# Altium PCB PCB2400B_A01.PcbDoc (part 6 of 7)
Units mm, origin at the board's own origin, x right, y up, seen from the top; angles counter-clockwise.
Board outline 115 x 60 mm, 6 copper layers (Top Layer, Signal Layer 2, Signal Layer 3, Signal Layer 4, Signal Layer 5, Bottom Layer), stack 1.555 mm thick; 382 components, 308 nets, 1384 pads, 1152 vias.
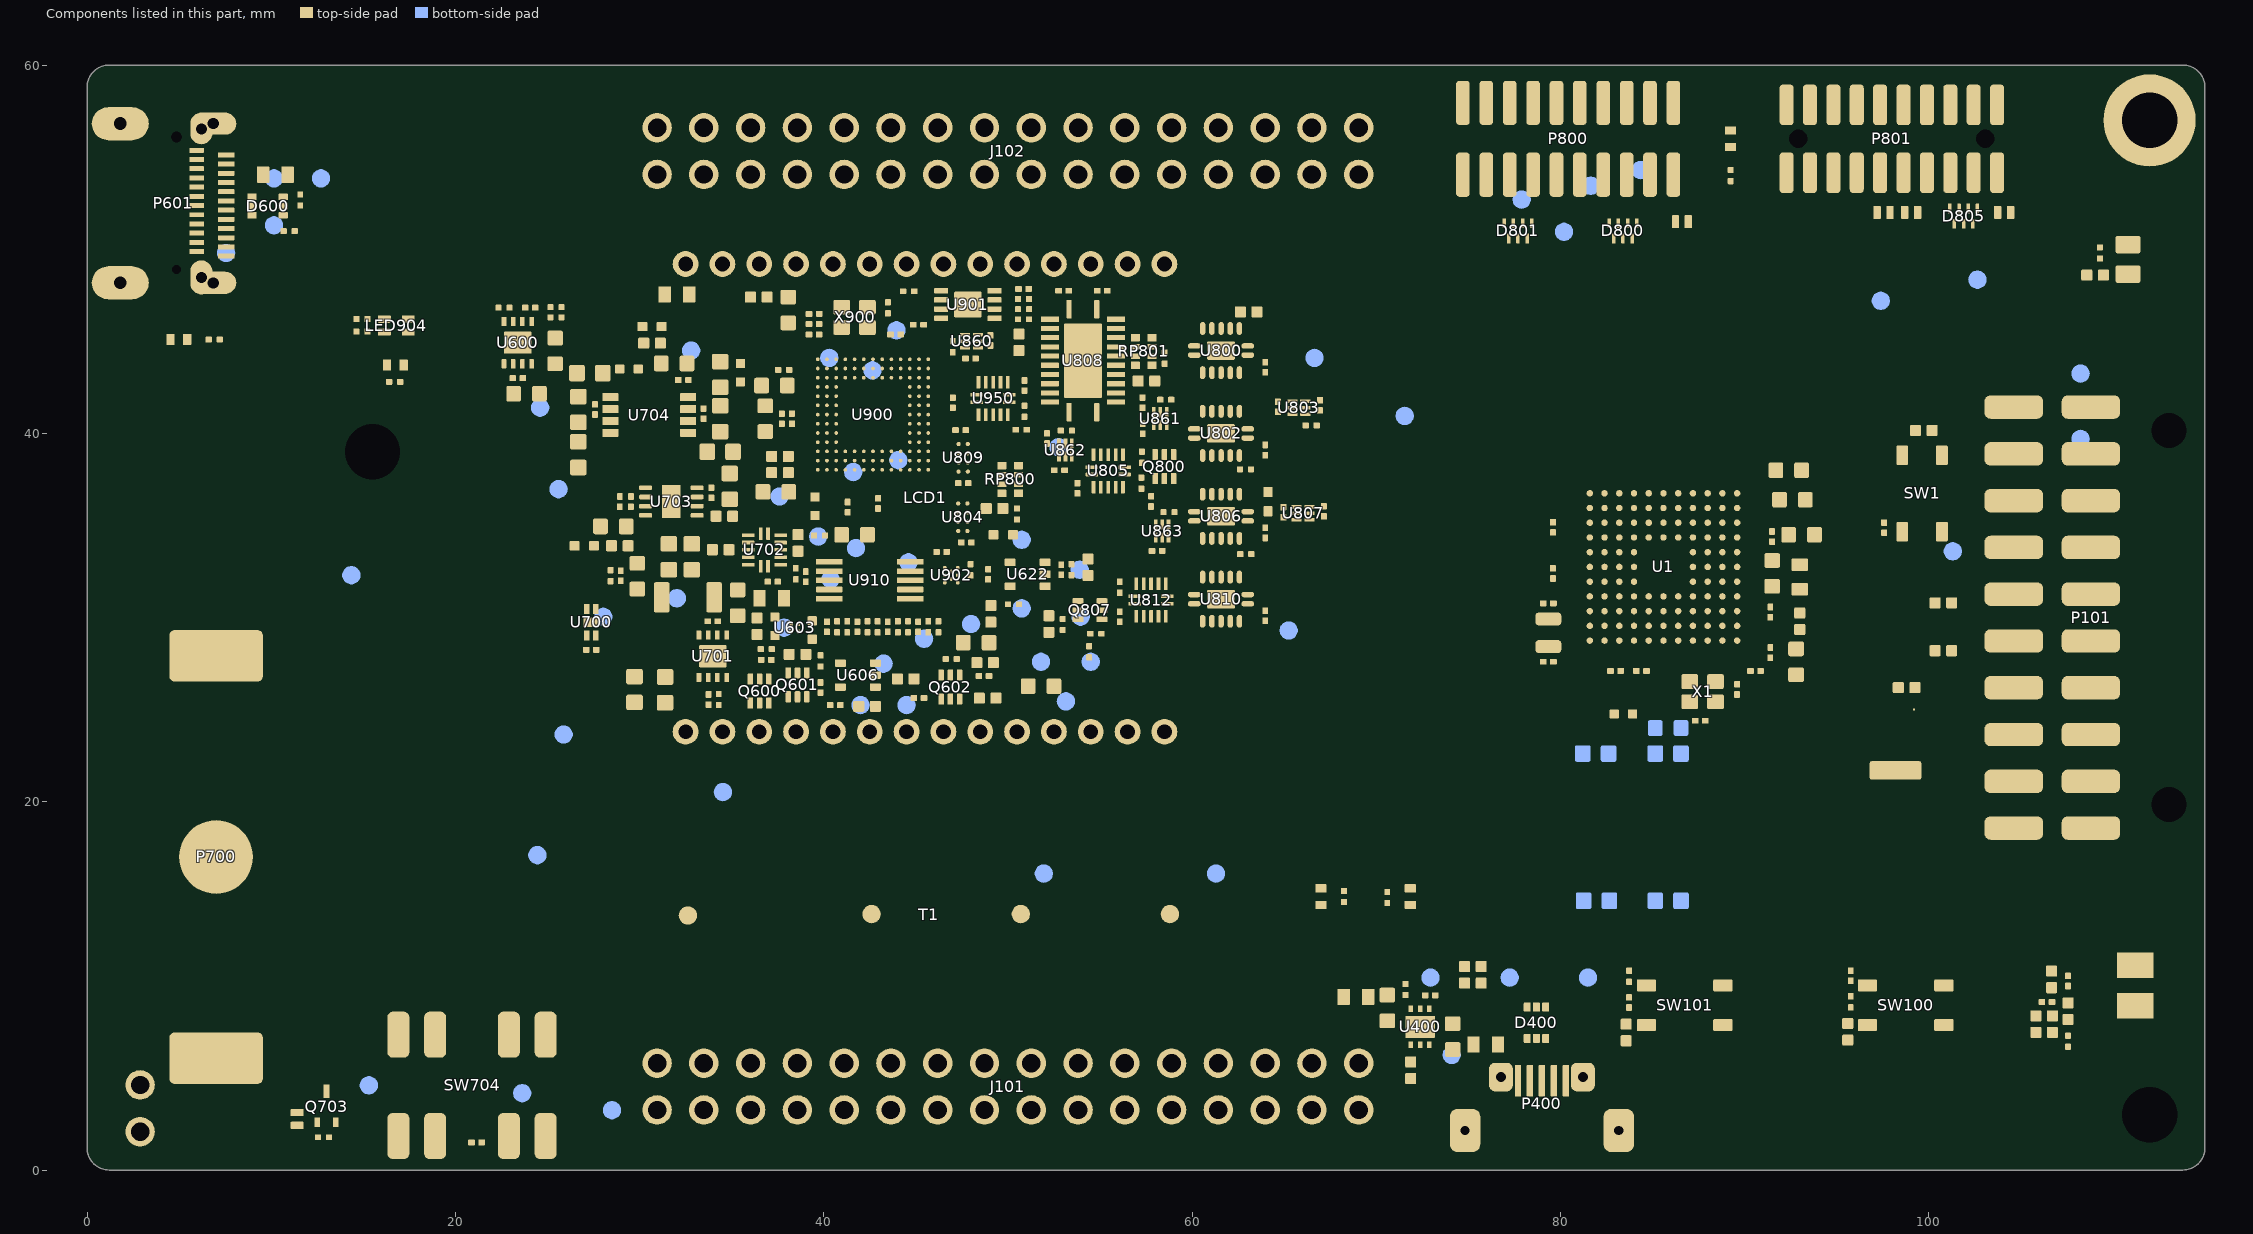
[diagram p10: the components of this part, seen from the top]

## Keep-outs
Bottom Layer:
  region: 68.25,54.063 ccw(c69.05,54.063) 69.05,53.263 ccw(c69.05,54.063) 69.85,54.063 ccw(c69.05,54.063) 69.05,54.863 ccw(c69.05,54.063)
  region: 65.71,54.063 ccw(c66.51,54.063) 66.51,53.263 ccw(c66.51,54.063) 67.31,54.063 ccw(c66.51,54.063) 66.51,54.863 ccw(c66.51,54.063)
  region: 42.85,54.063 ccw(c43.65,54.063) 43.65,53.263 ccw(c43.65,54.063) 44.45,54.063 ccw(c43.65,54.063) 43.65,54.863 ccw(c43.65,54.063)
  region: 40.31,54.063 ccw(c41.11,54.063) 41.11,53.263 ccw(c41.11,54.063) 41.91,54.063 ccw(c41.11,54.063) 41.11,54.863 ccw(c41.11,54.063)
  region: 37.77,54.063 ccw(c38.57,54.063) 38.57,53.263 ccw(c38.57,54.063) 39.37,54.063 ccw(c38.57,54.063) 38.57,54.863 ccw(c38.57,54.063)
  region: 35.23,54.063 ccw(c36.03,54.063) 36.03,53.263 ccw(c36.03,54.063) 36.83,54.063 ccw(c36.03,54.063) 36.03,54.863 ccw(c36.03,54.063)
  region: 32.69,54.063 ccw(c33.49,54.063) 33.49,53.263 ccw(c33.49,54.063) 34.29,54.063 ccw(c33.49,54.063) 33.49,54.863 ccw(c33.49,54.063)
  region: 68.25,56.603 ccw(c69.05,56.603) 69.05,55.803 ccw(c69.05,56.603) 69.85,56.603 ccw(c69.05,56.603) 69.05,57.403 ccw(c69.05,56.603)
  region: 65.71,56.603 ccw(c66.51,56.603) 66.51,55.803 ccw(c66.51,56.603) 67.31,56.603 ccw(c66.51,56.603) 66.51,57.403 ccw(c66.51,56.603)
  region: 63.17,56.603 ccw(c63.97,56.603) 63.97,55.803 ccw(c63.97,56.603) 64.77,56.603 ccw(c63.97,56.603) 63.97,57.403 ccw(c63.97,56.603)
  region: 60.63,56.603 ccw(c61.43,56.603) 61.43,55.803 ccw(c61.43,56.603) 62.23,56.603 ccw(c61.43,56.603) 61.43,57.403 ccw(c61.43,56.603)
  region: 58.09,56.603 ccw(c58.89,56.603) 58.89,55.803 ccw(c58.89,56.603) 59.69,56.603 ccw(c58.89,56.603) 58.89,57.403 ccw(c58.89,56.603)
  region: 53.01,56.603 ccw(c53.81,56.603) 53.81,55.803 ccw(c53.81,56.603) 54.61,56.603 ccw(c53.81,56.603) 53.81,57.403 ccw(c53.81,56.603)
  region: 50.47,56.603 ccw(c51.27,56.603) 51.27,55.803 ccw(c51.27,56.603) 52.07,56.603 ccw(c51.27,56.603) 51.27,57.403 ccw(c51.27,56.603)
  region: 47.93,56.603 ccw(c48.73,56.603) 48.73,55.803 ccw(c48.73,56.603) 49.53,56.603 ccw(c48.73,56.603) 48.73,57.403 ccw(c48.73,56.603)
  region: 45.39,56.603 ccw(c46.19,56.603) 46.19,55.803 ccw(c46.19,56.603) 46.99,56.603 ccw(c46.19,56.603) 46.19,57.403 ccw(c46.19,56.603)
  region: 42.85,56.603 ccw(c43.65,56.603) 43.65,55.803 ccw(c43.65,56.603) 44.45,56.603 ccw(c43.65,56.603) 43.65,57.403 ccw(c43.65,56.603)
  region: 40.31,56.603 ccw(c41.11,56.603) 41.11,55.803 ccw(c41.11,56.603) 41.91,56.603 ccw(c41.11,56.603) 41.11,57.403 ccw(c41.11,56.603)
  region: 37.77,56.603 ccw(c38.57,56.603) 38.57,55.803 ccw(c38.57,56.603) 39.37,56.603 ccw(c38.57,56.603) 38.57,57.403 ccw(c38.57,56.603)
  region: 35.23,56.603 ccw(c36.03,56.603) 36.03,55.803 ccw(c36.03,56.603) 36.83,56.603 ccw(c36.03,56.603) 36.03,57.403 ccw(c36.03,56.603)
  region: 32.69,56.603 ccw(c33.49,56.603) 33.49,55.803 ccw(c33.49,56.603) 34.29,56.603 ccw(c33.49,56.603) 33.49,57.403 ccw(c33.49,56.603)
  region: 68.25,3.263 ccw(c69.05,3.263) 69.05,2.463 ccw(c69.05,3.263) 69.85,3.263 ccw(c69.05,3.263) 69.05,4.063 ccw(c69.05,3.263)
  region: 65.71,3.263 ccw(c66.51,3.263) 66.51,2.463 ccw(c66.51,3.263) 67.31,3.263 ccw(c66.51,3.263) 66.51,4.063 ccw(c66.51,3.263)
  region: 63.17,3.263 ccw(c63.97,3.263) 63.97,2.463 ccw(c63.97,3.263) 64.77,3.263 ccw(c63.97,3.263) 63.97,4.063 ccw(c63.97,3.263)
  region: 60.63,3.263 ccw(c61.43,3.263) 61.43,2.463 ccw(c61.43,3.263) 62.23,3.263 ccw(c61.43,3.263) 61.43,4.063 ccw(c61.43,3.263)
  region: 58.09,3.263 ccw(c58.89,3.263) 58.89,2.463 ccw(c58.89,3.263) 59.69,3.263 ccw(c58.89,3.263) 58.89,4.063 ccw(c58.89,3.263)
  region: 55.55,3.263 ccw(c56.35,3.263) 56.35,2.463 ccw(c56.35,3.263) 57.15,3.263 ccw(c56.35,3.263) 56.35,4.063 ccw(c56.35,3.263)
  region: 53.01,3.263 ccw(c53.81,3.263) 53.81,2.463 ccw(c53.81,3.263) 54.61,3.263 ccw(c53.81,3.263) 53.81,4.063 ccw(c53.81,3.263)
  region: 50.47,3.263 ccw(c51.27,3.263) 51.27,2.463 ccw(c51.27,3.263) 52.07,3.263 ccw(c51.27,3.263) 51.27,4.063 ccw(c51.27,3.263)
  region: 47.93,3.263 ccw(c48.73,3.263) 48.73,2.463 ccw(c48.73,3.263) 49.53,3.263 ccw(c48.73,3.263) 48.73,4.063 ccw(c48.73,3.263)
  region: 45.39,3.263 ccw(c46.19,3.263) 46.19,2.463 ccw(c46.19,3.263) 46.99,3.263 ccw(c46.19,3.263) 46.19,4.063 ccw(c46.19,3.263)
  region: 42.85,3.263 ccw(c43.65,3.263) 43.65,2.463 ccw(c43.65,3.263) 44.45,3.263 ccw(c43.65,3.263) 43.65,4.063 ccw(c43.65,3.263)
  region: 40.31,3.263 ccw(c41.11,3.263) 41.11,2.463 ccw(c41.11,3.263) 41.91,3.263 ccw(c41.11,3.263) 41.11,4.063 ccw(c41.11,3.263)
  region: 37.77,3.263 ccw(c38.57,3.263) 38.57,2.463 ccw(c38.57,3.263) 39.37,3.263 ccw(c38.57,3.263) 38.57,4.063 ccw(c38.57,3.263)
  region: 35.23,3.263 ccw(c36.03,3.263) 36.03,2.463 ccw(c36.03,3.263) 36.83,3.263 ccw(c36.03,3.263) 36.03,4.063 ccw(c36.03,3.263)
  region: 32.69,3.263 ccw(c33.49,3.263) 33.49,2.463 ccw(c33.49,3.263) 34.29,3.263 ccw(c33.49,3.263) 33.49,4.063 ccw(c33.49,3.263)
  region: 30.15,5.803 ccw(c30.95,5.803) 30.95,5.003 ccw(c30.95,5.803) 31.75,5.803 ccw(c30.95,5.803) 30.95,6.603 ccw(c30.95,5.803)
  region: 68.25,5.803 ccw(c69.05,5.803) 69.05,5.003 ccw(c69.05,5.803) 69.85,5.803 ccw(c69.05,5.803) 69.05,6.603 ccw(c69.05,5.803)
  region: 65.71,5.803 ccw(c66.51,5.803) 66.51,5.003 ccw(c66.51,5.803) 67.31,5.803 ccw(c66.51,5.803) 66.51,6.603 ccw(c66.51,5.803)
  region: 63.17,5.803 ccw(c63.97,5.803) 63.97,5.003 ccw(c63.97,5.803) 64.77,5.803 ccw(c63.97,5.803) 63.97,6.603 ccw(c63.97,5.803)
  region: 60.63,5.803 ccw(c61.43,5.803) 61.43,5.003 ccw(c61.43,5.803) 62.23,5.803 ccw(c61.43,5.803) 61.43,6.603 ccw(c61.43,5.803)
  region: 58.09,5.803 ccw(c58.89,5.803) 58.89,5.003 ccw(c58.89,5.803) 59.69,5.803 ccw(c58.89,5.803) 58.89,6.603 ccw(c58.89,5.803)
  region: 55.55,5.803 ccw(c56.35,5.803) 56.35,5.003 ccw(c56.35,5.803) 57.15,5.803 ccw(c56.35,5.803) 56.35,6.603 ccw(c56.35,5.803)
  region: 53.01,5.803 ccw(c53.81,5.803) 53.81,5.003 ccw(c53.81,5.803) 54.61,5.803 ccw(c53.81,5.803) 53.81,6.603 ccw(c53.81,5.803)
  region: 50.47,5.803 ccw(c51.27,5.803) 51.27,5.003 ccw(c51.27,5.803) 52.07,5.803 ccw(c51.27,5.803) 51.27,6.603 ccw(c51.27,5.803)
  region: 47.93,5.803 ccw(c48.73,5.803) 48.73,5.003 ccw(c48.73,5.803) 49.53,5.803 ccw(c48.73,5.803) 48.73,6.603 ccw(c48.73,5.803)
  region: 45.39,5.803 ccw(c46.19,5.803) 46.19,5.003 ccw(c46.19,5.803) 46.99,5.803 ccw(c46.19,5.803) 46.19,6.603 ccw(c46.19,5.803)
  region: 42.85,5.803 ccw(c43.65,5.803) 43.65,5.003 ccw(c43.65,5.803) 44.45,5.803 ccw(c43.65,5.803) 43.65,6.603 ccw(c43.65,5.803)
  region: 40.31,5.803 ccw(c41.11,5.803) 41.11,5.003 ccw(c41.11,5.803) 41.91,5.803 ccw(c41.11,5.803) 41.11,6.603 ccw(c41.11,5.803)
  region: 37.77,5.803 ccw(c38.57,5.803) 38.57,5.003 ccw(c38.57,5.803) 39.37,5.803 ccw(c38.57,5.803) 38.57,6.603 ccw(c38.57,5.803)
  region: 35.23,5.803 ccw(c36.03,5.803) 36.03,5.003 ccw(c36.03,5.803) 36.83,5.803 ccw(c36.03,5.803) 36.03,6.603 ccw(c36.03,5.803)
  region: 32.69,5.803 ccw(c33.49,5.803) 33.49,5.003 ccw(c33.49,5.803) 34.29,5.803 ccw(c33.49,5.803) 33.49,6.603 ccw(c33.49,5.803)
  region: 103.499,19.001 cw(c103.499,18.501) 103.999,18.501 cw(c103.499,18.501) 103.499,18.001 cw(c103.499,18.501) 102.999,18.501 cw(c103.499,18.501)
  region: 108.249,40.201 cw(c108.249,39.7) 108.749,39.701 cw(c108.249,39.701) 108.249,39.201 cw(c108.249,39.701) 107.749,39.701 cw(c108.249,39.7)
  region: 108.249,43.749 cw(c108.249,43.249) 108.749,43.249 cw(c108.249,43.249) 108.249,42.749 cw(c108.249,43.249) 107.749,43.249 cw(c108.249,43.249)
  region: 106.999,54.201 cw(c106.999,53.701) 107.499,53.701 cw(c106.999,53.701) 106.999,53.201 cw(c106.999,53.701) 106.499,53.701 cw(c106.999,53.701)
  region: 105.399,52.499 cw(c105.399,51.999) 105.899,51.999 cw(c105.399,51.999) 105.399,51.499 cw(c105.399,51.999) 104.899,51.999 cw(c105.399,51.999)
  region: 104.449,54.201 cw(c104.449,53.701) 104.949,53.701 cw(c104.449,53.701) 104.449,53.201 cw(c104.449,53.701) 103.949,53.701 cw(c104.449,53.701)
  region: 103.398,52.499 cw(c103.398,51.999) 103.898,51.999 cw(c103.398,51.999) 103.398,51.499 cw(c103.398,51.999) 102.898,51.999 cw(c103.398,51.999)
  region: 102.648,48.849 cw(c102.648,48.349) 103.148,48.349 cw(c102.648,48.349) 102.648,47.849 cw(c102.648,48.349) 102.148,48.349 cw(c102.648,48.349)
  region: 97.398,47.701 cw(c97.398,47.201) 97.898,47.201 cw(c97.398,47.201) 97.398,46.701 cw(c97.398,47.201) 96.898,47.201 cw(c97.398,47.201)
  region: 92.524,52.433 cw(c92.524,51.933) 93.024,51.933 cw(c92.524,51.933) 92.524,51.433 cw(c92.524,51.933) 92.024,51.933 cw(c92.524,51.933)
  region: 93.54,54.211 cw(c93.54,53.711) 94.04,53.711 cw(c93.54,53.711) 93.54,53.211 cw(c93.54,53.711) 93.04,53.711 cw(c93.54,53.711)
  region: 90.492,52.433 cw(c90.492,51.933) 90.992,51.933 cw(c90.492,51.933) 90.492,51.433 cw(c90.492,51.933) 89.992,51.933 cw(c90.492,51.933)
  region: 88.46,52.433 cw(c88.46,51.933) 88.96,51.933 cw(c88.46,51.933) 88.46,51.433 cw(c88.46,51.933) 87.96,51.933 cw(c88.46,51.933)
  region: 89.476,54.211 cw(c89.476,53.711) 89.976,53.711 cw(c89.476,53.711) 89.476,53.211 cw(c89.476,53.711) 88.976,53.711 cw(c89.476,53.711)
  region: 87.465,54.207 cw(c87.466,53.707) 87.966,53.707 cw(c87.465,53.708) 87.465,53.207 cw(c87.465,53.707) 86.966,53.707 cw(c87.466,53.707)
  region: 84.348,54.8 cw(c84.348,54.3) 84.848,54.301 cw(c84.348,54.301) 84.348,53.8 cw(c84.348,54.3) 83.848,54.3 cw(c84.348,54.3)
  region: 85.399,52.199 cw(c85.399,51.699) 85.899,51.7 cw(c85.399,51.7) 85.399,51.2 cw(c85.399,51.699) 84.899,51.699 cw(c85.399,51.699)
  region: 93.448,42.799 cw(c93.448,42.299) 93.949,42.299 cw(c93.448,42.299) 93.448,41.799 cw(c93.448,42.299) 92.948,42.299 cw(c93.449,42.299)
  region: 86.148,40.051 cw(c86.149,39.551) 86.649,39.551 cw(c86.148,39.551) 86.148,39.051 cw(c86.148,39.551) 85.649,39.551 cw(c86.149,39.551)
  region: 81.648,53.95 cw(c81.648,53.45) 82.148,53.45 cw(c81.648,53.45) 81.648,52.95 cw(c81.648,53.45) 81.148,53.45 cw(c81.648,53.449)
  region: 77.899,53.2 cw(c77.899,52.7) 78.399,52.7 cw(c77.898,52.7) 77.899,52.2 cw(c77.899,52.7) 77.399,52.7 cw(c77.899,52.7)
  region: 80.2,51.45 cw(c80.2,50.95) 80.7,50.95 cw(c80.2,50.95) 80.2,50.45 cw(c80.2,50.95) 79.7,50.95 cw(c80.2,50.95)
  region: 77.398,48.499 cw(c77.398,47.999) 77.898,47.999 cw(c77.398,47.999) 77.398,47.499 cw(c77.398,47.999) 76.898,47.999 cw(c77.398,47.999)
  region: 75.399,48.499 cw(c75.399,47.999) 75.899,47.999 cw(c75.399,47.999) 75.399,47.499 cw(c75.399,47.999) 74.899,47.999 cw(c75.399,47.999)
  region: 73.398,48.499 cw(c73.398,47.999) 73.898,47.999 cw(c73.398,47.999) 73.398,47.499 cw(c73.398,47.999) 72.898,47.999 cw(c73.398,47.999)
  region: 77.398,46.299 cw(c77.398,45.799) 77.898,45.799 cw(c77.398,45.799) 77.398,45.299 cw(c77.398,45.799) 76.898,45.799 cw(c77.398,45.799)
  region: 75.399,46.299 cw(c75.399,45.799) 75.899,45.799 cw(c75.399,45.799) 75.399,45.299 cw(c75.399,45.799) 74.899,45.799 cw(c75.399,45.799)
  region: 73.398,46.299 cw(c73.398,45.799) 73.898,45.799 cw(c73.398,45.799) 73.398,45.299 cw(c73.398,45.799) 72.898,45.799 cw(c73.398,45.799)
  region: 71.399,46.299 cw(c71.399,45.799) 71.899,45.799 cw(c71.399,45.799) 71.399,45.299 cw(c71.399,45.799) 70.899,45.799 cw(c71.399,45.799)
  region: 73.398,43.599 cw(c73.398,43.099) 73.898,43.099 cw(c73.398,43.099) 73.398,42.599 cw(c73.398,43.099) 72.898,43.099 cw(c73.398,43.099)
  region: 71.549,41.45 cw(c71.549,40.95) 72.049,40.95 cw(c71.548,40.95) 71.549,40.45 cw(c71.549,40.95) 71.049,40.95 cw(c71.549,40.95)
  region: 66.649,44.6 cw(c66.649,44.1) 67.149,44.1 cw(c66.649,44.1) 66.649,43.6 cw(c66.649,44.1) 66.149,44.1 cw(c66.649,44.1)
  region: 94.198,12.349 cw(c94.198,11.849) 94.698,11.849 cw(c94.198,11.85) 94.198,11.349 cw(c94.198,11.849) 93.698,11.849 cw(c94.198,11.849)
  region: 96.799,11.801 cw(c96.799,11.301) 97.299,11.301 cw(c96.799,11.301) 96.799,10.801 cw(c96.799,11.301) 96.299,11.301 cw(c96.799,11.301)
  region: 93.248,9.949 cw(c93.248,9.449) 93.748,9.449 cw(c93.248,9.449) 93.248,8.949 cw(c93.248,9.449) 92.748,9.449 cw(c93.248,9.449)
  region: 96.499,9.149 cw(c96.499,8.649) 96.999,8.649 cw(c96.499,8.649) 96.499,8.149 cw(c96.499,8.649) 95.999,8.649 cw(c96.499,8.649)
  region: 95.699,6.551 cw(c95.699,6.051) 96.199,6.051 cw(c95.699,6.051) 95.699,5.551 cw(c95.699,6.051) 95.199,6.051 cw(c95.699,6.05)
  region: 93.248,7.399 cw(c93.248,6.899) 93.748,6.899 cw(c93.248,6.899) 93.248,6.399 cw(c93.248,6.899) 92.748,6.899 cw(c93.248,6.899)
  region: 81.498,10.95 cw(c81.498,10.45) 81.998,10.45 cw(c81.498,10.45) 81.498,9.95 cw(c81.498,10.45) 80.998,10.45 cw(c81.498,10.45)
  region: 77.248,10.95 cw(c77.248,10.45) 77.748,10.45 cw(c77.248,10.45) 77.248,9.95 cw(c77.248,10.45) 76.748,10.45 cw(c77.248,10.45)
  region: 72.948,10.95 cw(c72.948,10.45) 73.448,10.45 cw(c72.948,10.45) 72.948,9.95 cw(c72.948,10.45) 72.448,10.45 cw(c72.948,10.45)
  region: 74.099,6.749 cw(c74.099,6.249) 74.599,6.249 cw(c74.099,6.249) 74.099,5.749 cw(c74.099,6.249) 73.599,6.249 cw(c74.099,6.249)
  region: 54.673,41.625 cw(c54.673,41.125) 55.173,41.126 cw(c54.673,41.126) 54.673,40.626 cw(c54.673,41.125) 54.173,41.125 cw(c54.673,41.125)
  region: 52.747,39.751 cw(c52.748,39.251) 53.248,39.251 cw(c52.747,39.251) 52.747,38.751 cw(c52.747,39.251) 52.248,39.251 cw(c52.748,39.251)
  region: 50.749,34.724 cw(c50.749,34.224) 51.249,34.224 cw(c50.748,34.224) 50.749,33.724 cw(c50.749,34.224) 50.249,34.224 cw(c50.749,34.224)
  region: 53.898,33.099 cw(c53.898,32.599) 54.398,32.599 cw(c53.898,32.599) 53.898,32.099 cw(c53.898,32.599) 53.398,32.599 cw(c53.898,32.599)
  region: 50.749,31.001 cw(c50.749,30.501) 51.249,30.501 cw(c50.748,30.501) 50.749,30.001 cw(c50.749,30.501) 50.249,30.501 cw(c50.749,30.501)
  region: 53.949,30.551 cw(c53.949,30.051) 54.449,30.051 cw(c53.949,30.051) 53.949,29.551 cw(c53.949,30.051) 53.449,30.051 cw(c53.949,30.051)
  region: 54.498,28.1 cw(c54.498,27.6) 54.998,27.6 cw(c54.497,27.6) 54.498,27.1 cw(c54.498,27.6) 53.998,27.6 cw(c54.498,27.6)
  region: 51.798,28.1 cw(c51.798,27.6) 52.298,27.6 cw(c51.797,27.6) 51.798,27.1 cw(c51.798,27.6) 51.298,27.6 cw(c51.798,27.6)
  region: 53.149,25.951 cw(c53.149,25.451) 53.649,25.451 cw(c53.149,25.451) 53.149,24.951 cw(c53.149,25.451) 52.649,25.451 cw(c53.149,25.451)
  region: 47.998,30.15 cw(c47.998,29.65) 48.498,29.65 cw(c47.998,29.65) 47.998,29.15 cw(c47.998,29.65) 47.498,29.65 cw(c47.998,29.65)
  region: 45.448,29.35 cw(c45.448,28.85) 45.948,28.85 cw(c45.447,28.85) 45.448,28.35 cw(c45.448,28.85) 44.948,28.85 cw(c45.448,28.85)
  region: 46.999,25.75 cw(c47,25.25) 47.5,25.251 cw(c46.999,25.251) 46.999,24.751 cw(c46.999,25.25) 46.499,25.25 cw(c47,25.25)
  region: 43.248,28.001 cw(c43.248,27.501) 43.748,27.501 cw(c43.248,27.501) 43.248,27.001 cw(c43.248,27.501) 42.748,27.501 cw(c43.248,27.501)
  region: 44.498,25.75 cw(c44.498,25.25) 44.998,25.251 cw(c44.497,25.251) 44.498,24.751 cw(c44.498,25.25) 43.998,25.25 cw(c44.498,25.25)
  region: 41.998,25.75 cw(c41.998,25.25) 42.498,25.251 cw(c41.998,25.251) 41.998,24.751 cw(c41.998,25.25) 41.498,25.25 cw(c41.998,25.25)
  region: 61.3,16.599 cw(c61.3,16.099) 61.8,16.099 cw(c61.3,16.099) 61.3,15.599 cw(c61.3,16.099) 60.8,16.099 cw(c61.3,16.099)
  region: 51.95,16.599 cw(c51.95,16.099) 52.45,16.099 cw(c51.95,16.099) 51.95,15.599 cw(c51.95,16.099) 51.45,16.099 cw(c51.95,16.099)
  region: 34.523,21.026 cw(c34.523,20.526) 35.023,20.526 cw(c34.523,20.526) 34.523,20.026 cw(c34.523,20.526) 34.023,20.526 cw(c34.523,20.526)
  region: 24.449,17.6 cw(c24.449,17.1) 24.949,17.1 cw(c24.449,17.1) 24.449,16.6 cw(c24.449,17.1) 23.949,17.1 cw(c24.449,17.099)
  region: 15.648,26.449 cw(c15.648,25.949) 16.148,25.949 cw(c15.648,25.949) 15.648,25.449 cw(c15.648,25.949) 15.148,25.949 cw(c15.648,25.949)
  region: 12.049,26.449 cw(c12.049,25.949) 12.549,25.949 cw(c12.049,25.949) 12.049,25.449 cw(c12.049,25.949) 11.549,25.949 cw(c12.049,25.949)
  region: 12.024,29.774 cw(c12.024,29.274) 12.524,29.274 cw(c12.024,29.274) 12.024,28.774 cw(c12.024,29.274) 11.524,29.274 cw(c12.024,29.274)
  region: 9.474,29.799 cw(c9.474,29.299) 9.974,29.299 cw(c9.473,29.299) 9.474,28.799 cw(c9.474,29.299) 8.974,29.299 cw(c9.474,29.299)
  region: 14.348,32.799 cw(c14.348,32.299) 14.848,32.299 cw(c14.348,32.299) 14.348,31.799 cw(c14.348,32.299) 13.848,32.299 cw(c14.348,32.299)
  region: 10.398,32.25 cw(c10.398,31.75) 10.898,31.75 cw(c10.398,31.751) 10.398,31.25 cw(c10.398,31.75) 9.898,31.75 cw(c10.398,31.75)
  region: 10.398,34.9 cw(c10.398,34.4) 10.898,34.4 cw(c10.398,34.4) 10.398,33.9 cw(c10.398,34.4) 9.898,34.4 cw(c10.398,34.399)
  region: 18.445,49.045 cw(c18.445,48.545) 18.945,48.545 cw(c18.445,48.545) 18.445,48.045 cw(c18.445,48.545) 17.945,48.545 cw(c18.445,48.545)
  region: 15.905,50.315 cw(c15.905,49.815) 16.405,49.815 cw(c15.905,49.815) 15.905,49.315 cw(c15.905,49.815) 15.405,49.815 cw(c15.905,49.815)
  region: 18.445,51.585 cw(c18.445,51.085) 18.945,51.085 cw(c18.445,51.085) 18.445,50.585 cw(c18.445,51.085) 17.945,51.085 cw(c18.445,51.085)
  region: 15.905,52.855 cw(c15.905,52.355) 16.405,52.355 cw(c15.905,52.355) 15.905,51.855 cw(c15.905,52.355) 15.405,52.355 cw(c15.905,52.355)
  region: 18.445,54.125 cw(c18.445,53.625) 18.945,53.625 cw(c18.445,53.625) 18.445,53.125 cw(c18.445,53.625) 17.945,53.625 cw(c18.445,53.625)
  region: 15.905,55.395 cw(c15.905,54.895) 16.405,54.895 cw(c15.905,54.895) 15.905,54.395 cw(c15.905,54.895) 15.405,54.895 cw(c15.905,54.895)
  region: 12.699,54.351 cw(c12.699,53.851) 13.199,53.851 cw(c12.699,53.851) 12.699,53.351 cw(c12.699,53.851) 12.199,53.851 cw(c12.699,53.851)
  region: 10.149,54.351 cw(c10.149,53.851) 10.649,53.851 cw(c10.149,53.851) 10.149,53.351 cw(c10.149,53.851) 9.649,53.851 cw(c10.149,53.851)
  region: 10.149,51.801 cw(c10.149,51.301) 10.649,51.301 cw(c10.149,51.301) 10.149,50.801 cw(c10.149,51.301) 9.649,51.301 cw(c10.149,51.301)
  region: 7.548,50.3 cw(c7.548,49.8) 8.048,49.8 cw(c7.548,49.8) 7.548,49.3 cw(c7.548,49.8) 7.048,49.8 cw(c7.548,49.799)
  region: 24.599,41.9 cw(c24.599,41.4) 25.099,41.4 cw(c24.599,41.4) 24.599,40.9 cw(c24.599,41.4) 24.099,41.4 cw(c24.599,41.4)
  region: 36.248,37.549 cw(c36.248,37.049) 36.748,37.049 cw(c36.248,37.049) 36.248,36.549 cw(c36.248,37.049) 35.748,37.049 cw(c36.248,37.049)
  region: 38.974,37.544 cw(c38.974,37.044) 39.474,37.044 cw(c38.974,37.045) 38.974,36.544 cw(c38.974,37.044) 38.474,37.044 cw(c38.974,37.044)
  region: 41.599,38.4 cw(c41.599,37.9) 42.1,37.9 cw(c41.599,37.9) 41.599,37.4 cw(c41.599,37.9) 41.099,37.9 cw(c41.6,37.9)
  region: 44.048,39.05 cw(c44.048,38.55) 44.548,38.55 cw(c44.048,38.55) 44.048,38.05 cw(c44.048,38.55) 43.548,38.55 cw(c44.048,38.55)
  region: 42.648,43.924 cw(c42.648,43.424) 43.149,43.424 cw(c42.648,43.424) 42.648,42.924 cw(c42.648,43.424) 42.148,43.424 cw(c42.649,43.424)
  region: 43.949,46.101 cw(c43.949,45.601) 44.449,45.601 cw(c43.949,45.601) 43.949,45.101 cw(c43.949,45.601) 43.449,45.601 cw(c43.949,45.601)
  region: 18.445,46.505 cw(c18.445,46.005) 18.945,46.005 cw(c18.445,46.005) 18.445,45.505 cw(c18.445,46.005) 17.945,46.005 cw(c18.445,46.005)

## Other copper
Top Layer:
  pour cut-out: 49.006,49.758 49.006,49.626 49.941,49.626 49.941,49.758
  pour cut-out: 81.277,39.88 81.277,39.748 82.213,39.748 82.213,39.88
  pour cut-out: 82.507,38.77 82.375,38.77 82.375,37.834 82.507,37.834
  pour cut-out: 79.273,36.008 79.405,36.008 79.405,36.944 79.273,36.944
  pour cut-out: 87.991,31.141 87.991,31.009 88.927,31.009 88.927,31.141
  pour cut-out: 83.065,31.244 83.065,31.112 84.001,31.112 84.001,31.244
  pour cut-out: 82.54,32.712 82.408,32.712 82.408,31.776 82.54,31.776
  pour cut-out: 84.06,32.563 84.06,32.695 83.124,32.695 83.124,32.563
  pour cut-out: 85.695,34.177 85.695,34.309 84.759,34.309 84.759,34.177
  pour cut-out: 110.23,39.736 110.23,39.868 109.294,39.868 109.294,39.736
  pour cut-out: 106.576,42.161 106.708,42.161 106.708,43.096 106.576,43.096
  pour cut-out: 63.206,28.537 63.338,28.537 63.338,29.473 63.206,29.473
  pour cut-out: 57.033,23.359 57.033,23.227 57.969,23.227 57.969,23.359
  pour cut-out: 50.37,25.758 50.238,25.758 50.238,24.594 50.37,24.594
  pour cut-out: 51.99,23.304 51.99,23.436 51.054,23.436 51.054,23.304
  pour cut-out: 48.884,31.949 48.884,32.081 47.948,32.081 47.948,31.949
  pour cut-out: 22.043,42.65 22.394,42.65 22.394,43.244 22.043,43.244
  pour cut-out: 37.212,25.167 37.212,25.035 38.148,25.035 38.148,25.167
  pour cut-out: 35.499,26.443 35.367,26.443 35.367,25.508 35.499,25.508
  pour cut-out: 36.015,28.276 36.015,28.408 35.079,28.408 35.079,28.276
  pour cut-out: 24.389,1.673 24.389,1.805 23.453,1.805 23.453,1.673
  pour cut-out: 18.373,2.914 18.373,3.046 17.437,3.046 17.437,2.914
  pour cut-out: 9.055,50.703 9.055,50.835 8.119,50.835 8.119,50.703
  pour cut-out: 11.829,53.105 11.829,53.554 10.893,53.554 10.893,53.105
  pour cut-out: 9.742,55.322 9.742,55.19 10.678,55.19 10.678,55.322
  region net GND: 5.175,57.546 5.174,57.545 5.174,56.648 5.671,56.648 6.2,57.177 6.2,57.962
  region net GND: 6.147,47.052 6.147,48.181 6.03,48.298 5.208,48.298 5.208,47.629 5.691,47.146
  pour cut-out: 6.287,50.001 6.356,49.932 7.153,49.932 7.153,49.445 7.128,49.47 6.262,49.47 6.262,50.026 6.268,50.033
  pour cut-out: 6.312,55.508 6.382,55.438 7.179,55.438 7.179,54.951 7.153,54.977 6.287,54.977 6.287,55.533 6.293,55.539
  region net GND: 77.334,3.501 77.275,3.56 77.275,5.278 76.893,5.659 75.683,5.659 75.683,4.356 76.538,3.501
  region net GND: 80.892,3.808 80.709,3.991 80.709,5.459 80.824,5.574 80.824,6.185 81.934,6.185 82.118,6.001 82.118,3.939 81.987,3.808
  pour cut-out: 76.261,6.394 76.304,6.351 76.304,5.96 76.251,5.96 76.248,5.957 76.241,5.964 76.241,6.423
  region net N17454530: 3.458,7.725 3.458,5.542 4.5,4.5 10.538,4.5 10.538,7.725
  region net N17454530: 10.542,26.275 10.542,29.5 3.462,29.5 3.462,26.275
  pour cut-out: 26.858,34.179 26.858,33.612 27.16,33.612 27.166,33.619 27.166,34.179 26.858,34.179
  pour cut-out: 50.821,36.41 50.751,36.34 50.751,35.994 50.712,35.994 50.463,36.244 50.616,36.397 50.616,36.506
  pour cut-out: 81.468,55.288 85.634,55.288 85.95,54.972 85.731,54.753 85.731,52.811 81.64,52.811 81.537,52.914 81.537,55.186
  pour cut-out: 75.118,55.288 79.065,55.288 79.313,55.041 79.313,52.914 75.187,52.914 75.118,52.983
  pour cut-out: 29.804,35.277 29.793,35.266 29.793,33.608 30.944,33.608 31.012,33.676 30.813,33.875 30.813,34.488 30.593,34.488
  pour cut-out: 51.525,25.725 51.591,25.659 51.591,25.255 52.361,25.255 52.4,25.216 52.4,25.719 51.622,25.719 51.615,25.725
  pour cut-out: 59.973,28.916 59.973,28.935 60.192,29.154 60.434,28.912 61.112,28.912 61.112,28.758 60.833,28.478 60.169,28.478 60.169,28.72
  pour cut-out: 62.239,30.221 62.72,30.221 62.855,30.086 62.855,29.772 63.029,29.772 63.109,29.692 63.109,30.47 62.584,30.47 62.453,30.6 62.225,30.372
  pour cut-out: 65.012,37.074 64.964,37.026 64.964,35.995 63.621,35.995 63.337,36.279 63.337,36.658 63.752,37.074
  pour cut-out: 60.911,36.279 60.911,36.143 60.925,36.128 60.679,35.883 60.561,35.883 60.316,36.128 60.316,36.393 60.725,36.393 60.825,36.293
  pour cut-out: 59.823,36.857 59.866,36.9 60.295,36.9 60.295,37.609 60.205,37.698 59.636,37.698 59.636,37.025 59.65,37.011
  pour cut-out: 39.244,27.597 38.965,27.318 38.965,26.193 38.959,26.186 39.108,26.037 39.576,26.037 39.576,27.545 39.502,27.619 39.366,27.619 39.355,27.609 39.355,27.517
  pour cut-out: 45.076,26.246 45.096,26.227 45.096,25.832 46.031,25.832 46.128,25.929 46.113,25.943 46.113,26.111 45.673,26.111 45.567,26.217
  pour cut-out: 73.262,7.622 73.262,7.082 73.326,7.018 73.701,7.018 73.701,7.618 73.688,7.631 73.362,7.631 73.317,7.676
  pour cut-out: 100.323,55.3 102.027,55.3 102.027,53.186 101.941,53.1 101.933,53.109 100.107,53.109 100.107,55.258 100.219,55.37 100.393,55.196
  pour cut-out: 101.593,58.983 103.287,58.983 103.35,58.92 103.283,58.854 103.283,56.591 101.634,56.591 101.536,56.689 101.552,56.704 101.552,58.959
  pour cut-out: 93.137,58.983 93.176,58.944 93.176,56.581 92.74,56.581 92.643,56.678 92.643,58.929
  pour cut-out: 49.45,38.475 49.45,36.55 50.85,36.55 50.85,38.475
  pour cut-out: 56.675,45.4 56.675,43.475 58.075,43.475 58.075,45.4
  region net 3V3: 102.098,40.1 106.398,40.1 106.398,43.1 102.098,43.1
  pour cut-out: 78.65,30.275 78.65,28.075 80.05,28.075 80.05,30.275
  region net BC_I2C_EXP_SDA: 111.206,40.1 106.906,40.1 106.906,43.1 111.206,43.1
  region net GND: 111.206,19.9 106.906,19.9 106.906,16.9 111.206,16.9
  region net VMCU: 102.098,19.9 106.398,19.9 106.398,16.9 102.098,16.9
  pour cut-out: 30.7,9.4 30.7,18.4 60.7,18.4 60.7,9.4
  pour cut-out: 108.35,7.275 108.35,12.825 113.75,12.825 113.75,7.275
Signal Layer 2:
  pour cut-out: 30.7,9.4 30.7,18.4 60.7,18.4 60.7,9.4
  pour cut-out: 108.35,7.275 108.35,12.825 113.75,12.825 113.75,7.275
Signal Layer 3:
  pour cut-out: 54.206,47.42 54.405,47.221 54.604,47.221 54.604,47.004 54.665,46.943 54.197,46.943
  pour cut-out: 60.981,48.402 61.179,48.203 61.378,48.203 61.378,47.986 61.844,47.52 60.964,47.52
  pour cut-out: 100.079,29.463 100.278,29.264 100.476,29.264 100.476,29.048 100.538,28.986 100.07,28.986
  pour cut-out: 100.716,28.247 100.914,28.049 101.113,28.049 101.113,27.832 101.113,27.719 100.716,27.5
  pour cut-out: 102.906,24.861 103.105,24.663 103.304,24.663 103.304,24.446 103.365,24.384 102.897,24.384
  pour cut-out: 93.448,32.997 93.249,32.798 93.249,32.599 93.032,32.599 92.971,32.538 92.971,33.006
  pour cut-out: 90.596,36.755 90.794,36.954 90.794,37.153 91.011,37.153 91.073,37.214 91.073,36.746
  pour cut-out: 92.879,34.254 93.077,34.055 93.276,34.055 93.276,33.838 93.338,33.777 92.87,33.777
  pour cut-out: 65.815,54.203 65.616,54.402 65.418,54.402 65.418,54.619 65.356,54.68 65.824,54.68
  pour cut-out: 60.659,56.157 59.95,56.866 59.751,56.866 59.751,57.082 59.69,57.144 60.678,57.144
  pour cut-out: 44.567,56.806 44.766,56.608 45.428,56.608 45.428,56.329 44.558,56.329
  pour cut-out: 39.542,48.584 39.344,48.385 39.344,48.186 39.127,48.186 39.065,48.125 39.065,48.593
  pour cut-out: 58.203,54.451 39.177,54.355 39.177,54.731
  pour cut-out: 39.355,40.124 39.156,39.925 39.156,39.726 38.94,39.726 38.878,39.665 38.878,40.133
  pour cut-out: 74.582,14.157 74.384,13.958 74.384,13.759 74.167,13.759 74.105,13.698 74.105,14.166
  pour cut-out: 70.407,11.842 70.035,11.47 68.622,11.47 68.56,11.409 68.56,11.877
  pour cut-out: 45.741,3.556 45.741,3.218 36.798,3.218 36.798,3.725
  pour cut-out: 88.209,23.328 88.17,23.289 88.17,22.77 88.024,22.77 87.914,22.879 87.993,22.958 87.993,23.274
  pour cut-out: 80.523,22.158 80.496,22.131 80.496,21.663 80.856,21.663 80.838,21.681 80.838,22.248 80.622,22.248 80.586,22.212
  pour cut-out: 81.765,19.917 81.783,19.899 81.783,19.179 81.999,19.179 82.026,19.206 81.864,19.368 81.864,20.025 81.846,20.025 81.819,19.998
  pour cut-out: 45.774,21.096 45.756,21.078 45.756,20.232 46.116,20.232 45.963,20.385 45.963,21.258 45.702,21.258 45.729,21.231 45.747,21.231 45.747,21.123
  pour cut-out: 33.115,48.796 37.678,48.796 39.219,50.338 33.637,50.338 33.5,50.2
  pour cut-out: 39.517,52.863 39.517,51.662 39.582,51.597 39.591,51.606 39.708,51.606 39.708,52.924 39.643,52.989
  pour cut-out: 71.172,36.234 71.172,33.537 71.212,33.496 71.177,33.461 71.074,33.461 71.074,36.179 71.073,36.18
  pour cut-out: 72.072,39.303 72.072,36.606 72.112,36.565 72.077,36.53 71.974,36.53 71.974,39.248 71.973,39.249
  pour cut-out: 80.883,37.467 80.883,34.77 80.923,34.729 80.784,33.074 80.785,34.694 80.785,37.412 80.784,37.413
  pour cut-out: 89.375,41.269 89.375,38.572 89.416,38.532 89.38,38.496 89.278,38.496 89.278,41.214 89.276,41.215
  pour cut-out: 89.496,41.328 75.888,33.534 76.347,39.69
  pour cut-out: 62.856,24.372 62.874,24.354 62.874,22.923 63.126,22.923 63.063,22.986 63.063,24.363
  pour cut-out: 75.429,25.452 75.429,22.755 75.469,22.714 75.434,22.679 75.331,22.679 75.331,25.397 75.33,25.398
  pour cut-out: 62.73,27.108 62.73,26.674 62.569,26.512 62.305,26.512 62.305,27.074 62.271,27.108
  pour cut-out: 54,26.577 53.868,26.445 53.868,26.155 54.152,26.155 54.153,26.154 54.153,26.541
  pour cut-out: 71.487,16.589 71.487,15.714 71.383,15.61 70.893,15.61 70.893,16.263 70.83,16.326
  pour cut-out: 70.767,17.676 70.568,17.477 70.568,17.278 70.351,17.278 70.29,17.217 70.29,17.685
  pour cut-out: 40.689,2.655 40.599,2.745 39.339,2.745 39.339,2.385 39.408,2.454 40.644,2.454
  pour cut-out: 88.209,28.767 88.092,28.649 87.803,28.649 89.659,26.793 90.486,26.793 90.486,27.342 90.495,27.351 90.477,27.369 89.397,27.369 89.397,27.579
  pour cut-out: 54.019,38.734 54.065,38.688 54.065,38.154 55.652,38.154 55.896,38.398 55.652,38.643 55.652,39.778 55.478,39.778 55.188,39.488 54.873,39.488
  pour cut-out: 59.685,42.722 59.685,42.332 59.586,42.233 60.041,41.779 60.041,41.572 60.228,41.572 60.515,41.858 60.515,42.352 60.386,42.352 59.957,42.782
  pour cut-out: 60.561,40.77 60.561,40.329 60.278,40.045 63.355,40.045 63.355,40.268 63.434,40.347 63.093,40.687 62.821,40.687
  pour cut-out: 71.789,43.233 71.789,43.043 71.871,42.961 86.616,42.961 86.616,43.299 86.609,43.306 71.817,43.306
  pour cut-out: 72.205,52.233 72.158,52.186 72.158,51.867 73.343,50.682 73.556,50.682 73.556,51.118 72.429,52.245 72.328,52.245
  pour cut-out: 30.7,9.4 30.7,18.4 60.7,18.4 60.7,9.4
  pour cut-out: 108.35,7.275 108.35,12.825 113.75,12.825 113.75,7.275
Signal Layer 4:
  pour cut-out: 68.58,55.215 68.58,54.936 68.58,54.909 68.805,54.909 68.805,55.215
  pour cut-out: 73.82,56.581 73.82,56.302 73.82,56.275 74.045,56.275 74.045,56.581
  pour cut-out: 43.623,24.079 43.344,24.079 43.317,24.079 43.317,23.854 43.623,23.854
  pour cut-out: 45.372,35.704 45.093,35.704 45.066,35.704 45.066,35.479 45.372,35.479
  pour cut-out: 40.754,42.055 40.475,42.055 40.448,42.055 40.448,41.83 40.754,41.83
  pour cut-out: 50.356,56.633 44.556,56.633 44.529,56.633 44.529,56.408 50.356,56.408
  pour cut-out: 37.912,56.307 36.872,56.307 36.845,56.307 36.845,56.082 37.912,56.082
  pour cut-out: 63.659,46.381 63.659,47.827 63.659,48.213 63.434,48.213 63.434,46.381
  pour cut-out: 53.333,48.907 53.612,48.907 53.639,48.907 53.639,49.132 53.333,49.132
  pour cut-out: 51.322,48.922 51.601,48.922 51.628,48.922 51.628,49.147 51.322,49.147
  pour cut-out: 42.59,56.012 42.869,56.012 42.896,56.012 42.896,56.237 42.59,56.237
  pour cut-out: 43.018,52.18 43.018,51.901 43.018,51.874 43.243,51.874 43.243,52.18
  pour cut-out: 90.327,33.361 90.327,33.082 90.327,33.055 90.552,33.055 90.552,33.361
  pour cut-out: 90.585,35.775 90.585,35.496 90.585,35.469 90.81,35.469 90.81,35.775
  pour cut-out: 84.454,26.233 84.023,26.233 83.996,26.233 83.996,26.008 84.454,26.008
  pour cut-out: 83.183,10.788 83.183,11.698 83.183,11.725 82.958,11.725 82.958,10.788
  pour cut-out: 81.281,8.947 81.56,8.947 81.891,8.947 81.891,9.172 81.281,9.172
  pour cut-out: 89.39,45.255 89.669,45.255 89.696,45.255 89.696,45.48 89.39,45.48
  pour cut-out: 93.569,38.516 93.848,38.516 93.875,38.516 93.875,38.741 93.569,38.741
  pour cut-out: 96.487,17.539 96.766,17.539 96.793,17.539 96.793,17.764 96.487,17.764
  pour cut-out: 91.993,14.846 92.272,14.846 92.299,14.846 92.299,15.071 91.993,15.071
  pour cut-out: 89.717,7.435 89.996,7.435 91.214,7.435 91.214,7.66 89.717,7.66
  pour cut-out: 79.778,9.925 79.807,9.954 80.1,9.954 80.1,10.071 79.954,9.925 79.778,9.925 79.778,10.132 79.767,10.143 79.785,10.161 80.181,10.161 80.181,9.963 80.19,9.954 80.037,9.954
  pour cut-out: 108.477,52.65 108.868,52.713 108.896,52.686 109.125,53.388 108.527,52.938
  pour cut-out: 106.858,53.198 107.249,53.261 107.276,53.234 107.506,53.936 106.907,53.486
  pour cut-out: 92.475,26.586 92.866,26.649 92.894,26.622 93.123,27.324 92.525,26.874
  pour cut-out: 94.086,26.316 94.477,26.379 94.505,26.352 94.734,27.054 94.136,26.604
  pour cut-out: 87.219,22.248 87.611,22.311 87.638,22.284 87.867,22.986 87.269,22.536
  pour cut-out: 49.492,3.503 49.771,3.503 50.369,2.905 50.369,3.728 49.429,3.728
  pour cut-out: 52.738,3.262 53.017,3.262 53.044,3.235 53.044,3.487 52.675,3.487
  pour cut-out: 63.79,27.322 64.203,27.537 64.23,27.51 64.23,27.762 63.861,27.762
  pour cut-out: 49.888,7.278 50.167,7.278 50.194,7.251 50.194,7.551 49.812,7.551
  pour cut-out: 47.88,7.865 48.159,7.865 48.186,7.838 48.186,8.127 47.807,8.127
  pour cut-out: 78.486,23.418 78.765,23.418 78.792,23.391 78.792,23.643 78.423,23.643
  pour cut-out: 76.388,23.319 76.666,23.319 76.694,23.292 76.694,23.544 76.325,23.544
  pour cut-out: 74.245,22.423 74.688,22.423 74.688,22.675 74.175,22.675
  pour cut-out: 74.785,20.484 75.064,20.484 75.092,20.457 75.092,20.709 74.722,20.709
  pour cut-out: 73.759,17.91 74.038,17.91 74.475,17.473 74.475,18.135 73.696,18.135
  pour cut-out: 71.339,35.225 71.618,35.225 73.017,33.826 73.017,35.45 71.276,35.45
  pour cut-out: 67.921,35.836 68.2,35.836 68.501,35.535 68.501,36.061 67.858,36.061
  pour cut-out: 63.5,41.599 63.779,41.599 63.806,41.572 63.806,41.824 63.437,41.824
  pour cut-out: 63.46,43.857 63.94,43.857 64.011,43.787 64.011,44.082 63.397,44.082
  pour cut-out: 67.072,42.201 67.351,42.201 67.422,42.131 67.422,42.426 67.01,42.426
  pour cut-out: 83.043,30.75 83.322,30.75 83.349,30.723 83.349,30.975 82.98,30.975
  pour cut-out: 82.134,15.318 82.413,15.318 82.44,15.318 82.44,15.543 82.134,15.543
  pour cut-out: 81.425,17.273 81.486,17.334 81.873,17.334 81.873,17.568 81.882,17.577 81.756,17.703 81.315,17.703
  pour cut-out: 30.7,9.4 30.7,18.4 60.7,18.4 60.7,9.4
  pour cut-out: 108.35,7.275 108.35,12.825 113.75,12.825 113.75,7.275
Signal Layer 5:
  pour cut-out: 30.7,9.4 30.7,18.4 60.7,18.4 60.7,9.4
  pour cut-out: 108.35,7.275 108.35,12.825 113.75,12.825 113.75,7.275
Bottom Layer:
  pour cut-out: 80.432,52.066 81.04,52.066 81.04,51.547 80.432,51.547
  pour cut-out: 45.947,29.411 46.556,29.411 46.556,28.892 45.947,28.892
  pour cut-out: 49.641,35.057 50.249,35.057 50.249,34.538 49.641,34.538
  pour cut-out: 49.638,33.274 50.246,33.274 50.246,32.36 49.638,32.36
  pour cut-out: 46.66,46.803 47.268,46.803 47.268,46.283 46.66,46.283
  pour cut-out: 37.827,25.201 38.435,25.201 38.435,24.682 37.827,24.682
  pour cut-out: 36.777,34.186 37.385,34.186 37.385,33.667 36.777,33.667
  pour cut-out: 37.443,39.716 38.052,39.716 38.052,39.197 37.443,39.197
  pour cut-out: 36.549,38.902 37.158,38.902 37.158,38.383 36.549,38.383
  pour cut-out: 38.242,44.73 38.85,44.73 38.85,44.211 38.242,44.211
  pour cut-out: 50.449,41.23 51.057,41.23 51.057,40.71 50.449,40.71
  pour cut-out: 50.566,37.999 51.174,37.999 51.174,37.48 50.566,37.48
  pour cut-out: 47.337,36.687 47.945,36.687 47.945,36.168 47.337,36.168
  pour cut-out: 55.351,34.863 55.96,34.863 55.96,34.344 55.351,34.344
  pour cut-out: 54.242,33.016 54.851,33.016 54.851,32.496 54.242,32.496
  pour cut-out: 55.243,24.333 55.852,24.333 55.852,23.814 55.243,23.814
  pour cut-out: 57.222,23.847 57.83,23.847 57.83,23.328 57.222,23.328
  pour cut-out: 52.388,28.28 52.997,28.28 52.997,27.761 52.388,27.761
  pour cut-out: 57.164,37.184 58.314,37.184 58.314,36.665 57.164,36.665
  pour cut-out: 59.748,38.085 60.357,38.085 60.357,37.566 59.748,37.566
  pour cut-out: 53.189,39.391 53.798,39.391 53.798,38.872 53.189,38.872
  pour cut-out: 68.793,35.323 69.402,35.323 69.402,33.921 68.793,33.921
  pour cut-out: 67.914,36.189 68.523,36.189 68.523,35.67 67.914,35.67
  pour cut-out: 57.173,56.754 69.653,56.754 69.653,56.235 57.173,56.235
  pour cut-out: 55.646,58.216 56.255,58.216 56.255,57.257 55.646,57.257
  pour cut-out: 47.111,54.501 47.987,54.501 47.987,53.982 47.111,53.982
  pour cut-out: 49.72,54.554 50.329,54.554 50.329,54.035 49.72,54.035
  pour cut-out: 68.826,46.526 68.885,46.467 69.669,46.467 69.714,46.422 69.624,46.332 69.624,46.08 69.198,46.08 68.878,46.4
  pour cut-out: 51.776,39.909 51.782,39.903 52.425,39.903 52.425,39.789 52.336,39.7 51.866,39.7 51.628,39.938
  pour cut-out: 49.117,39.877 49.138,39.898 50.068,39.898 50.068,39.779 50.039,39.75 49.911,39.877 49.117,39.877 49.117,39.836 49.201,39.752
  pour cut-out: 48.696,31.987 48.847,32.139 48.696,31.987 48.895,31.788 49.095,31.788 49.158,31.851
  pour cut-out: 51.53,28.768 51.53,27.82 51.432,27.722 51.155,27.999 50.715,27.999 50.715,28.701 50.783,28.768
  pour cut-out: 57.744,55.045 57.744,53.356 59.55,51.55 59.514,51.514 59.15,51.514 56.821,53.843
  pour cut-out: 108.347,7.275 108.353,12.825 113.747,12.825 113.747,7.275

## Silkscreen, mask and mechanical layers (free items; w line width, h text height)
Top Overlay:
  lines w0.2: 87.2,56.025 88.65,56.025 ; 89.85,56.025 91.3,56.025
  text "5V" at 30.18,58.3 h1.2
  text "GND" at 32.385,58.3 h1.2
  text "D0" at 35.425,58.3 h1.2
  text "D1" at 37.965,58.3 h1.2
  text "D2" at 40.505,58.3 h1.2
  text "D3" at 43.045,58.3 h1.2
  text "D4" at 45.585,58.3 h1.2
  text "D5" at 48.125,58.3 h1.2
  text "D6" at 50.665,58.3 h1.2
  text "D7" at 53.205,58.3 h1.2
  text "D8" at 55.78,58.3 h1.2
  text "D13" at 57.985,58.3 h1.2
  text "D14" at 60.525,58.3 h1.2
  text "D15" at 63.065,58.3 h1.2
  text "GND" at 65.405,58.3 h1.2
  text "3V3" at 68.245,58.3 h1.2
  text "1" at 87.5,57.5 h1.5
  text "1" at 104.7,57.3 h1.5
  text "2" at 104.6,53.6 h1.5
  text "2" at 87.3,52.9 h1.5
  text "5V" at 30,51.6 h1.2
  text "GND" at 32.205,51.6 h1.2
  text "B9" at 35.425,51.6 h1.2
  text "B10" at 37.665,51.6 h1.2
  text "B11" at 40.205,51.6 h1.2
  text "NC" at 42.945,51.6 h1.2
  text "E8" at 45.585,51.6 h1.2
  text "E9" at 48.125,51.6 h1.2
  text "E10" at 50.465,51.6 h1.2
  text "E11" at 53.005,51.6 h1.2
  text "E12" at 55.48,51.6 h1.2
  text "E13" at 58.085,51.6 h1.2
  text "E14" at 60.625,51.6 h1.2
  text "E15" at 63.165,51.6 h1.2
  text "GND" at 65.405,51.6 h1.2
  text "3V3" at 68.245,51.6 h1.2
  text "SIMPLICITY" at 91.602,48.789 h1.6
  text "DEBUG" at 73.816,48.5 h1.6
  text "Light Sense" at 105,46.5 h2
  text "Wonder Gecko" at 75.2,41.9 h2.8
  text "RESET" at 96.237,32.13 h2
  text "EFM32WG990" at 80.8,22.78 h2
  text "2" at 104.5,16.4 h1.5
  text "1" at 108.3,16.4 h1.5
  text "LC Sense" at 106.146,13.329 h2
  text "LED1" at 65.252,12.172 h2
  text "LED0" at 70.05,12.172 h2
  text "BAT" at 15.7,9 h2
  text "USB" at 19.75,9 h2
  text "AEM" at 23.9,9 h2
  text "VMCU" at 28.785,7.5 h1.2
  text "GND" at 32.385,7.5 h1.2
  text "C0" at 35.45,7.5 h1.2
  text "C1" at 37.89,7.5 h1.2
  text "C2" at 40.43,7.5 h1.2
  text "C3" at 42.97,7.5 h1.2
  text "C4" at 45.51,7.5 h1.2
  text "C5" at 48.05,7.5 h1.2
  text "C6" at 50.59,7.5 h1.2
  text "C7" at 53.13,7.5 h1.2
  text "NC" at 55.57,7.5 h1.2
  text "F0" at 58.31,7.5 h1.2
  text "F1" at 60.85,7.5 h1.2
  text "F2" at 63.39,7.5 h1.2
  text "GND" at 65.405,7.5 h1.2
  text "3V3" at 68.245,7.5 h1.2
  text "BTN1" at 84.5,5 h2
  text "BTN0" at 96.5,5 h2
  text "VMCU" at 28.785,0.8 h1.2
  text "GND" at 32.385,0.8 h1.2
  text "A12" at 35.125,0.8 h1.2
  text "A13" at 37.665,0.8 h1.2
  text "A14" at 40.205,0.8 h1.2
  text "B15" at 43.045,0.8 h1.2
  text "E0" at 45.685,0.8 h1.2
  text "E1" at 48.225,0.8 h1.2
  text "E2" at 50.765,0.8 h1.2
  text "E3" at 53.205,0.8 h1.2
  text "NC" at 55.745,0.8 h1.2
  text "NC" at 58.285,0.8 h1.2
  text "F8" at 60.925,0.8 h1.2
  text "F9" at 63.465,0.8 h1.2
  text "GND" at 65.505,0.8 h1.2
  text "3V3" at 68.245,0.8 h1.2
Bottom Overlay:
  lines w0.152: 80.802,12.915 81.702,12.915 ; 80.802,20.943 81.702,20.943 ; 80.973,20.691 81.531,20.691 ; 81.009,12.636 81.567,12.636 ; 81.162,20.421 81.387,20.421 ; 81.171,12.348 81.396,12.348 ; 81.252,20.934 81.252,21.771 ; 81.27,12.942 81.27,13.779 ; 83.322,14.592 84.456,14.592 ; 83.322,22.592 84.456,22.592 ; 84.015,14.603 84.015,17.289 84.978,17.289 ; 84.033,22.591 84.033,19.872 84.996,19.872 ; 84.987,20.925 84.987,16.249 89.091,18.594 ; 85.005,20.925 89.097,18.587 ; 85.221,17.298 85.77,17.298 ; 85.23,19.881 85.779,19.881 ; 85.491,17.019 85.491,17.568 ; 87.219,22.592 89.719,22.592 ; 87.237,14.592 89.737,14.601 ; 89.088,18.592 91.338,18.592 ; 89.739,14.592 89.739,22.592 ; 102.099,20.399 106.9,20.399 ; 102.099,22.901 106.801,22.901 ; 102.099,25.401 106.9,25.401 ; 102.099,27.9 106.9,27.9 ; 102.099,30.399 106.9,30.399 ; 102.099,32.901 106.801,32.901 ; 102.099,35.401 106.9,35.401 ; 102.099,37.9 106.9,37.9 ; 102.099,40.399 106.9,40.399 ; 102.248,42.901 102.099,42.901 ; 103.451,22.901 106.9,22.901 ; 103.451,32.901 106.9,32.901 ; 104.5,17.9 104.5,42.901 ; 104.5,27.9 106.801,27.9 ; 102.099,42.901 106.9,42.901 106.9,17.9 102.099,17.9 102.099,42.901
  text "3V3" at 109.818,41.068 h1.7
  text "19" at 104.058,41.041 h1.7
  text "20" at 106.427,41.023 h1.7
  text "5V" at 110.925,38.845 h1.7
  text "18" at 106.443,38.557 h1.7
  text "17" at 104.103,38.538 h1.7
  text "I2C_SCL" at 101.484,36.077 h1.7
  text "15" at 104.094,36.073 h1.7
  text "16" at 106.506,36.064 h1.7
  text "I2C_SDA" at 113.382,36.059 h1.7
  text "13" at 104.031,33.607 h1.7
  text "14" at 106.47,33.561 h1.7
  text "UART_RX" at 114.183,33.422 h1.7
  text "12" at 106.443,30.987 h1.7
  text "11" at 104.103,30.969 h1.7
  text "UART_TX" at 113.949,30.92 h1.7
  text "10" at 106.47,28.585 h1.7
  text "SPI_CS" at 112.383,28.589 h1.7
  text "9" at 103.752,28.549 h1.7
  text "8" at 106.056,26.047 h1.7
  text "7" at 103.59,26.01 h1.7
  text "SPI_SCK" at 113.49,26.015 h1.7
  text "SPI_MISO" at 114.147,23.63 h1.7
  text "5" at 103.671,23.563 h1.7
  text "6" at 106.155,23.527 h1.7
  text "3" at 103.59,21.088 h1.7
  text "4" at 105.975,21.06 h1.7
  text "SPI_MOSI" at 114.138,20.975 h1.7
  text "2" at 106.022,18.675 h1.7
  text "1" at 103.527,18.63 h1.7
  text "VMCU" at 111.463,18.622 h1.7
  text "GND" at 101.646,18.559 h1.7
  text "BOARD INFO" at 19.8,15.7 h1.52
  text "BAT" at 7.4,4.1 h1.52
  text "GND" at 7.45,1.45 h1.52
  text "PCB2400B Rev A01" at 100.6,1.2 h1.52
Top Solder:
  lines w0.8: 0,1.2 ccw(c1.2,1.2) 1.2,0 113.8,0 ccw(c113.8,1.2) 115,1.2 115,58.8 ccw(c113.8,58.8) 113.8,60 1.2,60 ccw(c1.2,58.8) 0,58.8 0,1.2
Bottom Solder:
  lines w0.8: 0,1.2 ccw(c1.2,1.2) 1.2,0 113.8,0 ccw(c113.8,1.2) 115,1.2 115,58.8 ccw(c113.8,58.8) 113.8,60 1.2,60 ccw(c1.2,58.8) 0,58.8 0,1.2
BOARD OUTLINE:
  circle w0.1: c15.5,39 r1.5
  circle w0.1: c112,57 r1.5
  lines w0.1: 0,1.2 ccw(c1.2,1.2) 1.2,0 ; 0,1.2 ccw(c1.2,1.2) 1.2,0 ; 0,1.2 ccw(c1.2,1.2) 1.2,0 ; 0,1.2 ccw(c1.2,1.2) 1.2,0 ; 0,1.2 0,58.8 ; 0,1.2 0,58.8 ; 0,1.2 0,58.8 ; 0,1.2 0,58.8 ; 0,58.8 cw(c1.2,58.8) 1.2,60 ; 0,58.8 cw(c1.2,58.8) 1.2,60 ; 0,58.8 cw(c1.2,58.8) 1.2,60 ; 0,58.8 cw(c1.2,58.8) 1.2,60 ; 1.2,0 113.8,0 ; 1.2,0 113.8,0 ; 1.2,0 113.8,0 ; 1.2,0 113.8,0 ; 1.2,60 113.8,60 ; 1.2,60 113.8,60 ; 1.2,60 113.8,60 ; 1.2,60 113.8,60 ; 113.8,0 ccw(c113.8,1.2) 115,1.2 ; 113.8,0 ccw(c113.8,1.2) 115,1.2 ; 113.8,0 ccw(c113.8,1.2) 115,1.2 ; 113.8,0 ccw(c113.8,1.2) 115,1.2 ; 113.8,60 cw(c113.8,58.8) 115,58.8 ; 113.8,60 cw(c113.8,58.8) 115,58.8 ; 113.8,60 cw(c113.8,58.8) 115,58.8 ; 113.8,60 cw(c113.8,58.8) 115,58.8 ; 115,1.2 115,58.8 ; 115,1.2 115,58.8 ; 115,1.2 115,58.8 ; 115,1.2 115,58.8
Route Tool Path:
  lines w0.1: 1.2,-2.4 8.5,-2.4
  lines w2.4: 8.5,-1.2 1.2,-1.2 cw(c1.2,1.2) -1.2,1.2 -1.2,58.8 cw(c1.2,58.8) 1.2,61.2 8.5,61.2 ; 15.5,-1.2 56.5,-1.2 ; 15.5,61.2 56.5,61.209 ; 63.5,-1.2 94.5,-1.2 ; 63.5,61.2 94.5,61.2 ; 101.5,-1.2 113.8,-1.2 ccw(c113.8,1.2) 116.2,1.2 116.2,58.8 ccw(c113.8,58.8) 113.8,61.2 101.5,61.2
Top Component Outline:
  circle w0.102: c15.5,39 r1.5
  circle w0.102: c112,57 r1.5
  circle w0.102: c112,57 r2.5
  lines w0.1: 111.619,57 112.381,57 ; 112,56.619 112,57.381
Top Courtyard:
  circle w0.05: c15.5,39 r3
  circle w0.05: c112,57 r2.75
Top Component Center (Mech19):
  lines w0.05: 111.5,57 112.5,57 ; 112,56.5 112,57.5
Assembly Drawing Frame (Top):
  lines w0.2: -76.675,-16.7 -75.05,-16.7 ; -76.675,29.975 -75.05,29.975 ; -76.675,76.65 -75.05,76.65 ; -75.075,-63.35 -75.075,123.35 ; -75.05,-63.35 190.075,-63.35 190.075,123.35 -75.05,123.35 ; -22.025,-64.95 -22.025,-63.35 ; -22.025,123.35 -22.025,124.95 ; 31,-64.95 31,-63.35 ; 31,123.35 31,124.95 ; 84.025,123.35 84.025,124.95 ; 137.05,123.35 137.05,124.95 ; 190.075,-16.675 191.7,-16.675 ; 190.075,30 191.7,30 ; 190.075,76.675 191.7,76.675 ; -76.675,-64.95 191.675,-64.95 191.675,124.95 -76.675,124.95 -76.675,-64.95 ; 84.025,-64.95 84.025,-63.35 84.025,-64.95 ; 137.05,-64.95 137.05,-63.35 137.05,-64.95
  text "5" at -48.661,124.084 h0.5
  text "4" at 4.364,124.059 h0.5
  text "3" at 57.389,124.059 h0.5
  text "2" at 110.414,124.059 h0.5
  text "1" at 163.539,124.059 h0.5
  text "D" at 190.789,99.959 h0.5
  text "D" at -75.961,99.934 h0.5
  text "C" at 190.789,53.259 h0.5
  text "C" at -75.961,53.234 h0.5
  text "B" at 190.789,6.584 h0.5
  text "B" at -75.961,6.559 h0.5
  text "A" at 190.789,-40.066 h0.5
  text "A" at -75.961,-40.091 h0.5
  text "5" at -48.661,-64.216 h0.5
  text "4" at 4.364,-64.241 h0.5
  text "3" at 57.389,-64.241 h0.5
  text "2" at 110.414,-64.241 h0.5
  text "1" at 163.539,-64.241 h0.5
Title Block (Top):
  drawing of 27 lines, arcs and shapes, not listed
  text "Board Title" at 120.475,-38.4 h2.5
  text "EFM32 Wonder Gecko Starter Kit" at 121.875,-43.95 h3.5
  text "Page Title" at 120.475,-48.125 h2.5
  text "Designed:" at 88.225,-51.875 h1.7
  text "Approved:" at 104.425,-51.875 h1.7
  text "Top Assembly" at 121.875,-52.025 h3.2
  text "SSK" at 89.75,-54.375 h2.2
  text "AKM" at 105.8,-54.375 h2.2
  text "Revision" at 178.375,-55.15 h1.7
  text "Document number" at 120.475,-55.425 h2.35
  text "Size" at 88.225,-56.625 h1.7
  text "Sheet Modified Date" at 93.15,-56.625 h1.7
  text "A01" at 178.65,-58.2 h2.7
  text "BRD2400B (PCB2400B Rev A01)" at 121.875,-58.3 h3.2
  text "A4" at 88.8,-58.475 h2
  text "'.Print_Date'" at 93.725,-58.475 h2
  text "Sheet" at 178.375,-60.825 h1.7
  text "COPYRIGHT SILICON LABORATORIES  INC. 2022" at 92.872,-61.833 h1.7
  text "CONFIDENTIAL -SUBJECT TO TERMS OF USE" at 132.854,-61.833 h1.7
  text "1" at 179.575,-62.775 h1.7
  text "of" at 182.7,-62.775 h1.7
  text "2" at 185.425,-62.775 h1.7
Assembly Drawing Frame (Bottom):
  lines w0.2: -76.675,-16.7 -75.05,-16.7 ; -76.675,29.975 -75.05,29.975 ; -76.675,76.65 -75.05,76.65 ; -75.075,-63.35 -75.075,123.35 ; -75.05,-63.35 190.075,-63.35 190.075,123.35 -75.05,123.35 ; -22.025,-64.95 -22.025,-63.35 ; -22.025,123.35 -22.025,124.95 ; 31,-64.95 31,-63.35 ; 31,123.35 31,124.95 ; 84.025,-64.95 84.025,-63.35 ; 84.025,123.35 84.025,124.95 ; 137.05,-64.95 137.05,-63.35 ; 137.05,123.35 137.05,124.95 ; 190.075,-16.675 191.7,-16.675 ; 190.075,30 191.7,30 ; 190.075,76.675 191.7,76.675 ; -76.675,-64.95 191.675,-64.95 191.675,124.95 -76.675,124.95 -76.675,-64.95
  text "5" at -48.336,124.084 h0.5
  text "4" at 4.689,124.059 h0.5
  text "3" at 57.714,124.059 h0.5
  text "2" at 110.739,124.059 h0.5
  text "1" at 163.714,124.059 h0.5
  text "D" at 191.114,99.959 h0.5
  text "D" at -75.636,99.934 h0.5
  text "C" at 191.114,53.259 h0.5
  text "C" at -75.636,53.234 h0.5
  text "B" at 191.114,6.584 h0.5
  text "B" at -75.636,6.559 h0.5
  text "A" at 191.114,-40.066 h0.5
  text "A" at -75.636,-40.091 h0.5
  text "5" at -48.336,-64.216 h0.5
  text "4" at 4.689,-64.241 h0.5
  text "3" at 57.714,-64.241 h0.5
  text "2" at 110.739,-64.241 h0.5
  text "1" at 163.714,-64.241 h0.5
Title Block (Bottom):
  drawing of 27 lines, arcs and shapes, not listed
  text "Board Title" at -5.45,-38.4 h2.5
  text "EFM32 Wonder Gecko Starter Kit" at -6.85,-43.95 h3.5
  text "Page Title" at -5.45,-48.125 h2.5
  text "Approved:" at 10.6,-51.875 h1.7
  text "Designed:" at 26.8,-51.875 h1.7
  text "Bottom Assembly" at -6.85,-52.025 h3.2
  text "AKM" at 9.225,-54.375 h2.2
  text "SSK" at 25.275,-54.375 h2.2
  text "Revision" at -63.35,-55.15 h1.7
  text "Document number" at -5.45,-55.425 h2.35
  text "Sheet Modified Date" at 21.875,-56.625 h1.7
  text "Size" at 26.8,-56.625 h1.7
  text "A01" at -63.614,-58.2 h2.7
  text "BRD2400B (PCB2400B Rev A01)" at -6.85,-58.3 h3.2
  text "'.Print_Date'" at 21.3,-58.475 h2
  text "A4" at 26.225,-58.475 h2
  text "Sheet" at -63.35,-60.825 h1.7
  text "COPYRIGHT SILICON LABORATORIES  INC. 2022" at 22.039,-61.761 h1.7
  text "CONFIDENTIAL -SUBJECT TO TERMS OF USE" at -18.526,-61.849 h1.7
  text "2" at -70.4,-62.775 h1.7
  text "of" at -67.675,-62.775 h1.7
  text "2" at -64.55,-62.775 h1.7
Assembly Drawing Frame:
  lines w0.2: -85,-73.725 200,-73.725 200,132.825 -85,132.825 -85,-73.725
